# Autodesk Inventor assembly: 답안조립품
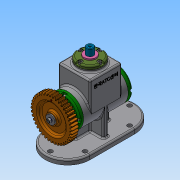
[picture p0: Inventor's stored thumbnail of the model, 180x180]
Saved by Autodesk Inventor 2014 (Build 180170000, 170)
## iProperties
Created: 2020-01
Part Number: 답안조립품
Document SubType Name: Assembly
Designer: net
Author: net
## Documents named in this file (18)
- C:\Users\net\Desktop\600104V1036\답안조립품.iam
- C:\Users\net\Desktop\600104V1036\본체.ipt
- C:\Users\net\Desktop\600104V1036\뒤커버.ipt
- C:\Users\net\Desktop\600104V1036\베어링 6203.ipt
- C:\Users\net\Desktop\600104V1036\볼트 M4.ipt
- C:\Users\net\Desktop\600104V1036\부시.ipt
- C:\Users\net\Desktop\600104V1036\슬라이더.ipt
- C:\Users\net\Desktop\600104V1036\스프링조립용 와셔.ipt
- C:\Users\net\Desktop\600104V1036\상부커버.ipt
- C:\Users\net\Desktop\600104V1036\편심축.ipt
- C:\Users\net\Desktop\600104V1036\키 4x4x12.ipt
- C:\Users\net\Desktop\600104V1036\앞커버.ipt
- C:\Users\net\Desktop\600104V1036\오일 실 17 30 5.ipt
- C:\Users\net\Desktop\600104V1036\스퍼기어.ipt
- C:\Users\net\Desktop\600104V1036\평와셔.ipt
- C:\Users\net\Desktop\600104V1036\스프링와셔.ipt
- C:\Users\net\Desktop\600104V1036\멈춤링.ipt
- C:\Users\net\Desktop\600104V1036\가변스프링.ipt
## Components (1 placed, 1 different names)
1. 가변스프링:1
